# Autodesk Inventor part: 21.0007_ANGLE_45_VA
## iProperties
Created: 2009-12
Part Number: 21.0007_ANGLE_45_VA
Document SubType Name: Modeling
Designer: Administrator
Density: 8.08 g/cm^3
Material: Stainless Steel
Mass: 402.481 g
Surface Area: 85.915 cm^2
Volume: 49.812 cm^3
Author: Administrator
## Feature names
1. Extrusion1
2. Extrusion2
3. Extrusion3
4. Extrusion4
5. Extrusion5
6. Extrusion6
7. Fillet1
8. Fillet2
9. Fillet3
10. Fillet4
